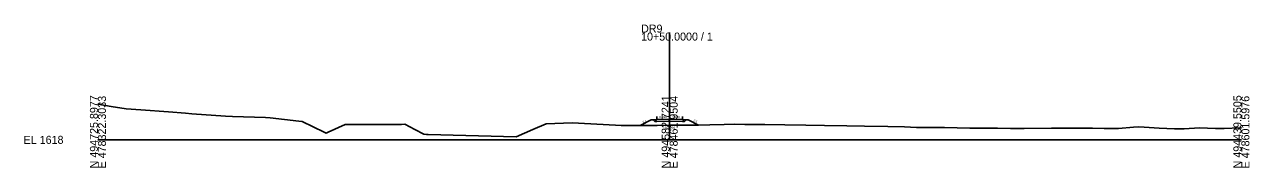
# Model space of a CAD drawing. Extents: x -26 to 403, y -10 to 1525.
# Drawn here: x -25.7 to 402.8, y 490.3 to 540.4 of the extents above; entities that cross this region are included whole.
import ezdxf

# ---------------------------------------------------------------- set-up
doc = ezdxf.new("R2010")
doc.units = 0
for name, color, linetype in [('Exist Cross Section Cell', 7, 'Continuous'), ('Exist XS Center Line Elevation Label', 7, 'Continuous'), ('Exist XS Ground Line', 7, 'Continuous'), ('Prop XS Dump Level', 7, 'Continuous'), ('Prop XS Earthwork Shape', 7, 'Continuous'), ('Prop XS EOT Tick Mark', 7, 'Continuous'), ('Prop XS Finish Grade', 7, 'Continuous'), ('Prop XS Finish Grade Earthwork', 7, 'Continuous'), ('Prop XS Finish Grade Pavement', 7, 'Continuous'), ('Prop XS Pvmt Edge Slope', 7, 'Continuous'), ('Prop XS SE Text', 7, 'Continuous'), ('Prop XS Shoulder Borrow Shape', 7, 'Continuous'), ('Prop XS Side Slope Text', 7, 'Continuous'), ('Prop XS Subgrade Earthwork', 7, 'Continuous'), ('Scratch_Level_5', 7, 'Continuous')]:
    doc.layers.add(name, color=color, linetype=linetype)

msp = doc.modelspace()

# ---------------------------------------------------------------- linework, layer by layer
at = {"layer": 'Exist Cross Section Cell'}
for p, q in [((200, 500), (200, 537.56)), ((0, 500), (200, 500)), ((200, 500), (400, 500))]:
    msp.add_line(p, q, dxfattribs=at)
at = {"layer": 'Exist XS Ground Line'}
msp.add_lwpolyline([(0, 512.52), (4.59, 511.73), (9.89, 510.83), (14.97, 510.48), (24.64, 509.8), (30.66, 509.3), (32.79, 509.12), (44.63, 508.3), (47.12, 508.16), (58.61, 507.85), (60.27, 507.76), (70.33, 506.5), (71.47, 506.43), (79.15, 502.73), (79.86, 502.39), (80.52, 502.68), (86.5, 505.33), (106.24, 505.42), (107.36, 505.45), (110.91, 503.61), (114.03, 501.98), (114.88, 501.9), (115.49, 501.92), (146.36, 501.11), (152.1, 503.65), (156.83, 505.64), (165.95, 505.99), (181, 505.14), (183.07, 505.05), (186.89, 505.03), (195.66, 505.07), (200, 505.09), (202.04, 505.1), (202.81, 505.11), (204.08, 505.13), (209.04, 505.16), (219.12, 505.33), (222.68, 505.45), (226.27, 505.41), (233.34, 505.39), (240.24, 505.31), (247.66, 505.18), (254.21, 505.08), (261.99, 504.96), (268.18, 504.78), (276.31, 504.66), (282.15, 504.54), (286.34, 504.36), (290.64, 504.36), (296.12, 504.31), (304.96, 504.04), (310.1, 504.04), (314.63, 504.13), (319.29, 504.02), (321.71, 503.92), (324.07, 504.03), (333.61, 504.09), (338.04, 504.04), (347.93, 504.04), (352.01, 504.02), (357.07, 504.01), (362.26, 504.41), (364.14, 504.5), (365.98, 504.41), (371.22, 504.04), (376.58, 503.91), (378.29, 503.9), (379.96, 503.91), (385.36, 504.19), (390.91, 503.98), (392.44, 504), (393.93, 503.99), (399.51, 504.18), (400, 504.18)], dxfattribs=at)
at = {"layer": 'Prop XS Dump Level'}
for p, q in [((200, 507.21), (195.5, 507.12)), ((204.5, 507.12), (200, 507.21))]:
    msp.add_line(p, q, dxfattribs=at)
at = {"layer": 'Prop XS Earthwork Shape'}
msp.add_lwpolyline([(189.66, 505.04), (195.66, 505.07), (200, 505.09), (202.04, 505.1), (202.81, 505.11), (204.08, 505.13), (209.04, 505.16), (210.07, 505.18), (206.5, 506.96), (205.76, 507.02), (205.18, 506.44), (204.5, 506.46), (200, 506.55), (195.5, 506.46), (194.82, 506.44), (194.24, 507.02), (193.5, 506.96)], close=True, dxfattribs=at)
at = {"layer": 'Prop XS EOT Tick Mark'}
for p, q in [((195.5, 507.12), (195.5, 508.12)), ((204.5, 507.12), (204.5, 508.12))]:
    msp.add_line(p, q, dxfattribs=at)
at = {"layer": 'Prop XS Finish Grade'}
for p, q in [((195.5, 507.12), (194.24, 507.02)), ((204.5, 507.12), (205.76, 507.02))]:
    msp.add_line(p, q, dxfattribs=at)
at = {"layer": 'Prop XS Finish Grade Earthwork'}
for p, q in [((193.5, 506.96), (189.66, 505.04)), ((194.24, 507.02), (193.5, 506.96)), ((205.76, 507.02), (206.5, 506.96)), ((206.5, 506.96), (210.07, 505.18))]:
    msp.add_line(p, q, dxfattribs=at)
at = {"layer": 'Prop XS Finish Grade Pavement'}
for p, q in [((195.5, 507.12), (200, 507.21)), ((200, 507.21), (204.5, 507.12))]:
    msp.add_line(p, q, dxfattribs=at)
at = {"layer": 'Prop XS Pvmt Edge Slope'}
for p, q in [((195.5, 507.12), (194.82, 506.44)), ((204.5, 507.12), (205.18, 506.44))]:
    msp.add_line(p, q, dxfattribs=at)
at = {"layer": 'Prop XS Shoulder Borrow Shape'}
for points in [[(195.5, 507.12), (194.82, 506.44), (194.24, 507.02)], [(205.18, 506.44), (205.76, 507.02), (204.5, 507.12)]]:
    msp.add_lwpolyline(points, close=True, dxfattribs=at)
at = {"layer": 'Prop XS Subgrade Earthwork'}
for p, q in [((194.82, 506.44), (194.24, 507.02)), ((195.5, 506.46), (194.82, 506.44)), ((200, 506.55), (195.5, 506.46)), ((204.5, 506.46), (200, 506.55)), ((204.5, 506.46), (205.18, 506.44)), ((205.18, 506.44), (205.76, 507.02))]:
    msp.add_line(p, q, dxfattribs=at)
at = {"layer": 'Scratch_Level_5'}
msp.add_lwpolyline([(0, 512.52), (4.59, 511.73), (9.89, 510.83), (14.97, 510.48), (24.64, 509.8), (30.66, 509.3), (32.79, 509.12), (44.63, 508.3), (47.12, 508.16), (58.61, 507.85), (60.27, 507.76), (70.33, 506.5), (71.47, 506.43), (79.15, 502.73), (79.86, 502.39), (80.52, 502.68), (86.5, 505.33), (106.24, 505.42), (107.36, 505.45), (110.91, 503.61), (114.03, 501.98), (114.88, 501.9), (115.49, 501.92), (146.36, 501.11), (152.1, 503.65), (156.83, 505.64), (165.95, 505.99), (181, 505.14), (183.07, 505.05), (186.89, 505.03), (195.66, 505.07), (200, 505.09), (202.04, 505.1), (202.81, 505.11), (204.08, 505.13), (209.04, 505.16), (219.12, 505.33), (222.68, 505.45), (226.27, 505.41), (233.34, 505.39), (240.24, 505.31), (247.66, 505.18), (254.21, 505.08), (261.99, 504.96), (268.18, 504.78), (276.31, 504.66), (282.15, 504.54), (286.34, 504.36), (290.64, 504.36), (296.12, 504.31), (304.96, 504.04), (310.1, 504.04), (314.63, 504.13), (319.29, 504.02), (321.71, 503.92), (324.07, 504.03), (333.61, 504.09), (338.04, 504.04), (347.93, 504.04), (352.01, 504.02), (357.07, 504.01), (362.26, 504.41), (364.14, 504.5), (365.98, 504.41), (371.22, 504.04), (376.58, 503.91), (378.29, 503.9), (379.96, 503.91), (385.36, 504.19), (390.91, 503.98), (392.44, 504), (393.93, 503.99), (399.51, 504.18), (400, 504.18)], dxfattribs=at)

# ---------------------------------------------------------------- texts
at = {"layer": 'Exist Cross Section Cell'}
for s, p in [('DR9', (190, 537.56)), ('10+50.0000 / 1', (190, 534.76)), ('EL 1618', (-26, 498.6))]:
    msp.add_text(s, height=2.8, dxfattribs=at).set_placement(p)
for s, p in [('N 494725.8977', (0, 490)), ('E 478322.3033', (2.8, 490)), ('N 494582.7241', (200, 490)), ('E 478461.9504', (202.8, 490)), ('N 494439.5505', (400, 490)), ('E 478601.5976', (402.8, 490))]:
    msp.add_text(s, height=2.8, rotation=90, dxfattribs=at).set_placement(p)
at = {"layer": 'Exist XS Center Line Elevation Label'}
msp.add_text('1623.09', height=0.75, dxfattribs=at).set_placement((198.2, 503.84))
at = {"layer": 'Prop XS Dump Level'}
for p in [(193.5, 506.92), (206.5, 506.92)]:
    msp.add_text('Case1', height=0.04, dxfattribs=at).set_placement(p)
at = {"layer": 'Prop XS SE Text'}
for rotation, p in [(1.1458, (196.44, 507.62)), (358.8542, (200.94, 507.67))]:
    msp.add_text('0.020', height=0.75, rotation=rotation, dxfattribs=at).set_placement(p)
at = {"layer": 'Prop XS Side Slope Text'}
for rotation, p in [(23.8531, (190.68, 505.83)), (333.4349, (208.24, 506.57))]:
    msp.add_text('2:1', height=0.75, rotation=rotation, dxfattribs=at).set_placement(p)

doc.saveas('drawing.dxf')
